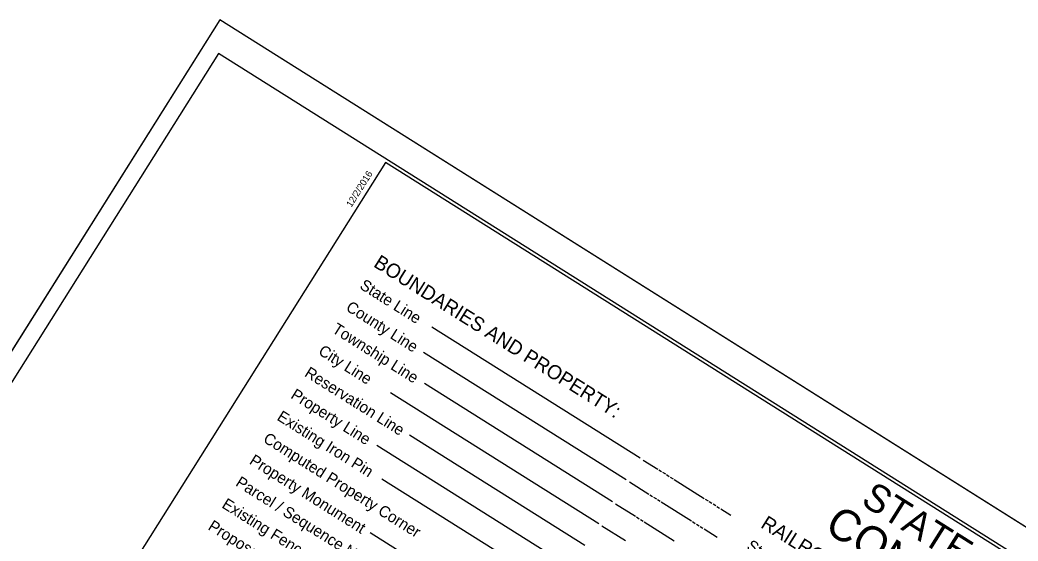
# Model space of a CAD drawing. Extents: x 2337092 to 2349158, y 800756 to 811724.
# Drawn here: x 2339681 to 2344308, y 809308 to 811724 of the extents above; entities that cross this region are included whole.
import ezdxf

# ---------------------------------------------------------------- set-up
doc = ezdxf.new("R2010")
doc.units = 0
for name, color, linetype in [('Sheet Cutting Line CELL', 7, 'Continuous'), ('Sheet Plot Border Inside CELL', 7, 'Continuous'), ('Sheet Plot Border Outside CELL', 7, 'Continuous'), ('Sheet Summary Guardrail CELL', 7, 'Continuous'), ('Sheet Symbology CELL', 7, 'Continuous')]:
    doc.layers.add(name, color=color, linetype=linetype)

msp = doc.modelspace()

# ---------------------------------------------------------------- linework, layer by layer
at = {"layer": 'Sheet Cutting Line CELL'}
for p, q in [((2340607.3, 811723.5), (2337091.6, 806137.8)), ((2349158.5, 806341.3), (2340607.3, 811723.5))]:
    msp.add_line(p, q, dxfattribs=at)
at = {"layer": 'Sheet Plot Border Inside CELL'}
msp.add_lwpolyline([(2337229.4, 806210.3), (2345691.7, 800884), (2349063.9, 806241.7), (2340601.5, 811568)], close=True, dxfattribs=at)
at = {"layer": 'Sheet Plot Border Outside CELL'}
msp.add_lwpolyline([(2337091.6, 806137.8), (2345642.8, 800755.6), (2349158.5, 806341.3), (2340607.3, 811723.5)], close=True, dxfattribs=at)
at = {"layer": 'Sheet Symbology CELL'}
for p, q in [((2342555.5, 809692.6), (2341590.8, 810299.8)), ((2342491.6, 809591), (2341552.2, 810182.3)), ((2342427.7, 809489.5), (2341555.8, 810038.2)), ((2342363.8, 809387.9), (2341399, 809995.1)), ((2342299.8, 809286.4), (2341487, 809798)), ((2342235.9, 809184.8), (2341335.9, 809751.3)), ((2342570.1, 809683.4), (2342637.2, 809641.2)), ((2342642.2, 809638), (2342654.9, 809630)), ((2342660, 809626.8), (2342672.7, 809618.8)), ((2342677.8, 809615.6), (2342690.5, 809607.7)), ((2342695.6, 809604.5), (2342708.3, 809596.5)), ((2342172, 809083.2), (2341359.2, 809594.9)), ((2342506.2, 809581.8), (2342595.5, 809525.6)), ((2342713.3, 809593.3), (2342853, 809505.4)), ((2342600.6, 809522.4), (2342613.3, 809514.4)), ((2342618.4, 809511.2), (2342631.1, 809503.3)), ((2342442.3, 809480.3), (2342533.9, 809422.6)), ((2342636.1, 809500.1), (2342648.8, 809492.1)), ((2342653.9, 809488.9), (2342793.6, 809401)), ((2342858, 809502.2), (2342870.7, 809494.2)), ((2342875.8, 809491), (2342888.5, 809483)), ((2342893.6, 809479.8), (2342906.3, 809471.8)), ((2342911.4, 809468.6), (2342924.1, 809460.6)), ((2342539, 809419.4), (2342551.7, 809411.4)), ((2342929.1, 809457.4), (2342976.4, 809427.7)), ((2342378.4, 809378.7), (2342488.2, 809309.6)), ((2342556.8, 809408.2), (2342569.5, 809400.2)), ((2342574.6, 809397), (2342714.2, 809309.1)), ((2342798.6, 809397.8), (2342811.3, 809389.8)), ((2342816.4, 809386.6), (2342829.1, 809378.6)), ((2342834.2, 809375.4), (2342846.9, 809367.4)), ((2342044.2, 808880.1), (2341304.4, 809345.7)), ((2342852, 809364.2), (2342912.4, 809326.2))]:
    msp.add_line(p, q, dxfattribs=at)
msp.add_lwpolyline([(2348992.3, 806268.7), (2341375.4, 811062.8), (2338022.8, 805736.2), (2345639.6, 800942.1)], close=True, dxfattribs=at)

# ---------------------------------------------------------------- texts
at = {"layer": 'Sheet Summary Guardrail CELL'}
msp.add_text('12/2/2016', height=31.5, rotation=57.8134, dxfattribs=at).set_placement((2341217.3, 810852.7))
at = {"layer": 'Sheet Symbology CELL'}
for s, height, p in [('BOUNDARIES AND PROPERTY:', 66, (2341315.7, 810582.5)), ('State Line', 52.5, (2341251.9, 810480.9)), ('County Line', 52.5, (2341188, 810379.4)), ('Township Line', 52.5, (2341124, 810277.8)), ('City Line', 52.5, (2341060.1, 810176.3)), ('Reservation Line', 52.5, (2340996.2, 810074.7)), ('Property Line', 52.5, (2340932.3, 809973.2)), ('Existing Iron Pin', 52.5, (2340868.3, 809871.6)), ('Computed Property Corner', 52.5, (2340804.4, 809770)), ('Property Monument', 52.5, (2340740.5, 809668.5)), ('Parcel / Sequence Number', 52.5, (2340676.6, 809566.9)), ('STATE OF NORTH CAROLINA, DIVISION OF HIGHWAYS', 128.514, (2343573.9, 809480.8)), ('Existing Fence Line', 52.5, (2340612.7, 809465.4)), ('RAILROADS:', 66, (2343110.4, 809373.3)), ('CONVENTIONAL  PLAN SHEET SYMBOLS', 146.882, (2343404.1, 809356.8)), ('Proposed Woven Wire Fence', 52.5, (2340548.7, 809363.8)), ('Standard Gauge', 52.5, (2343045.1, 809272.8))]:
    msp.add_text(s, height=height, rotation=327.8134, dxfattribs=at).set_placement(p)

doc.saveas('drawing.dxf')
